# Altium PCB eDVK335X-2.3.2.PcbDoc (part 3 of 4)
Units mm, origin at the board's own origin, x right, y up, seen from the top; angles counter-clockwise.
Board outline 100.04 x 80.07 mm, 4 copper layers (Top Layer, Layer 1, Layer 2, Bottom Layer), stack 0.569 mm thick; 245 components, 272 nets, 1313 pads, 662 vias.
Unrouted connection lines stored in the file: 1.
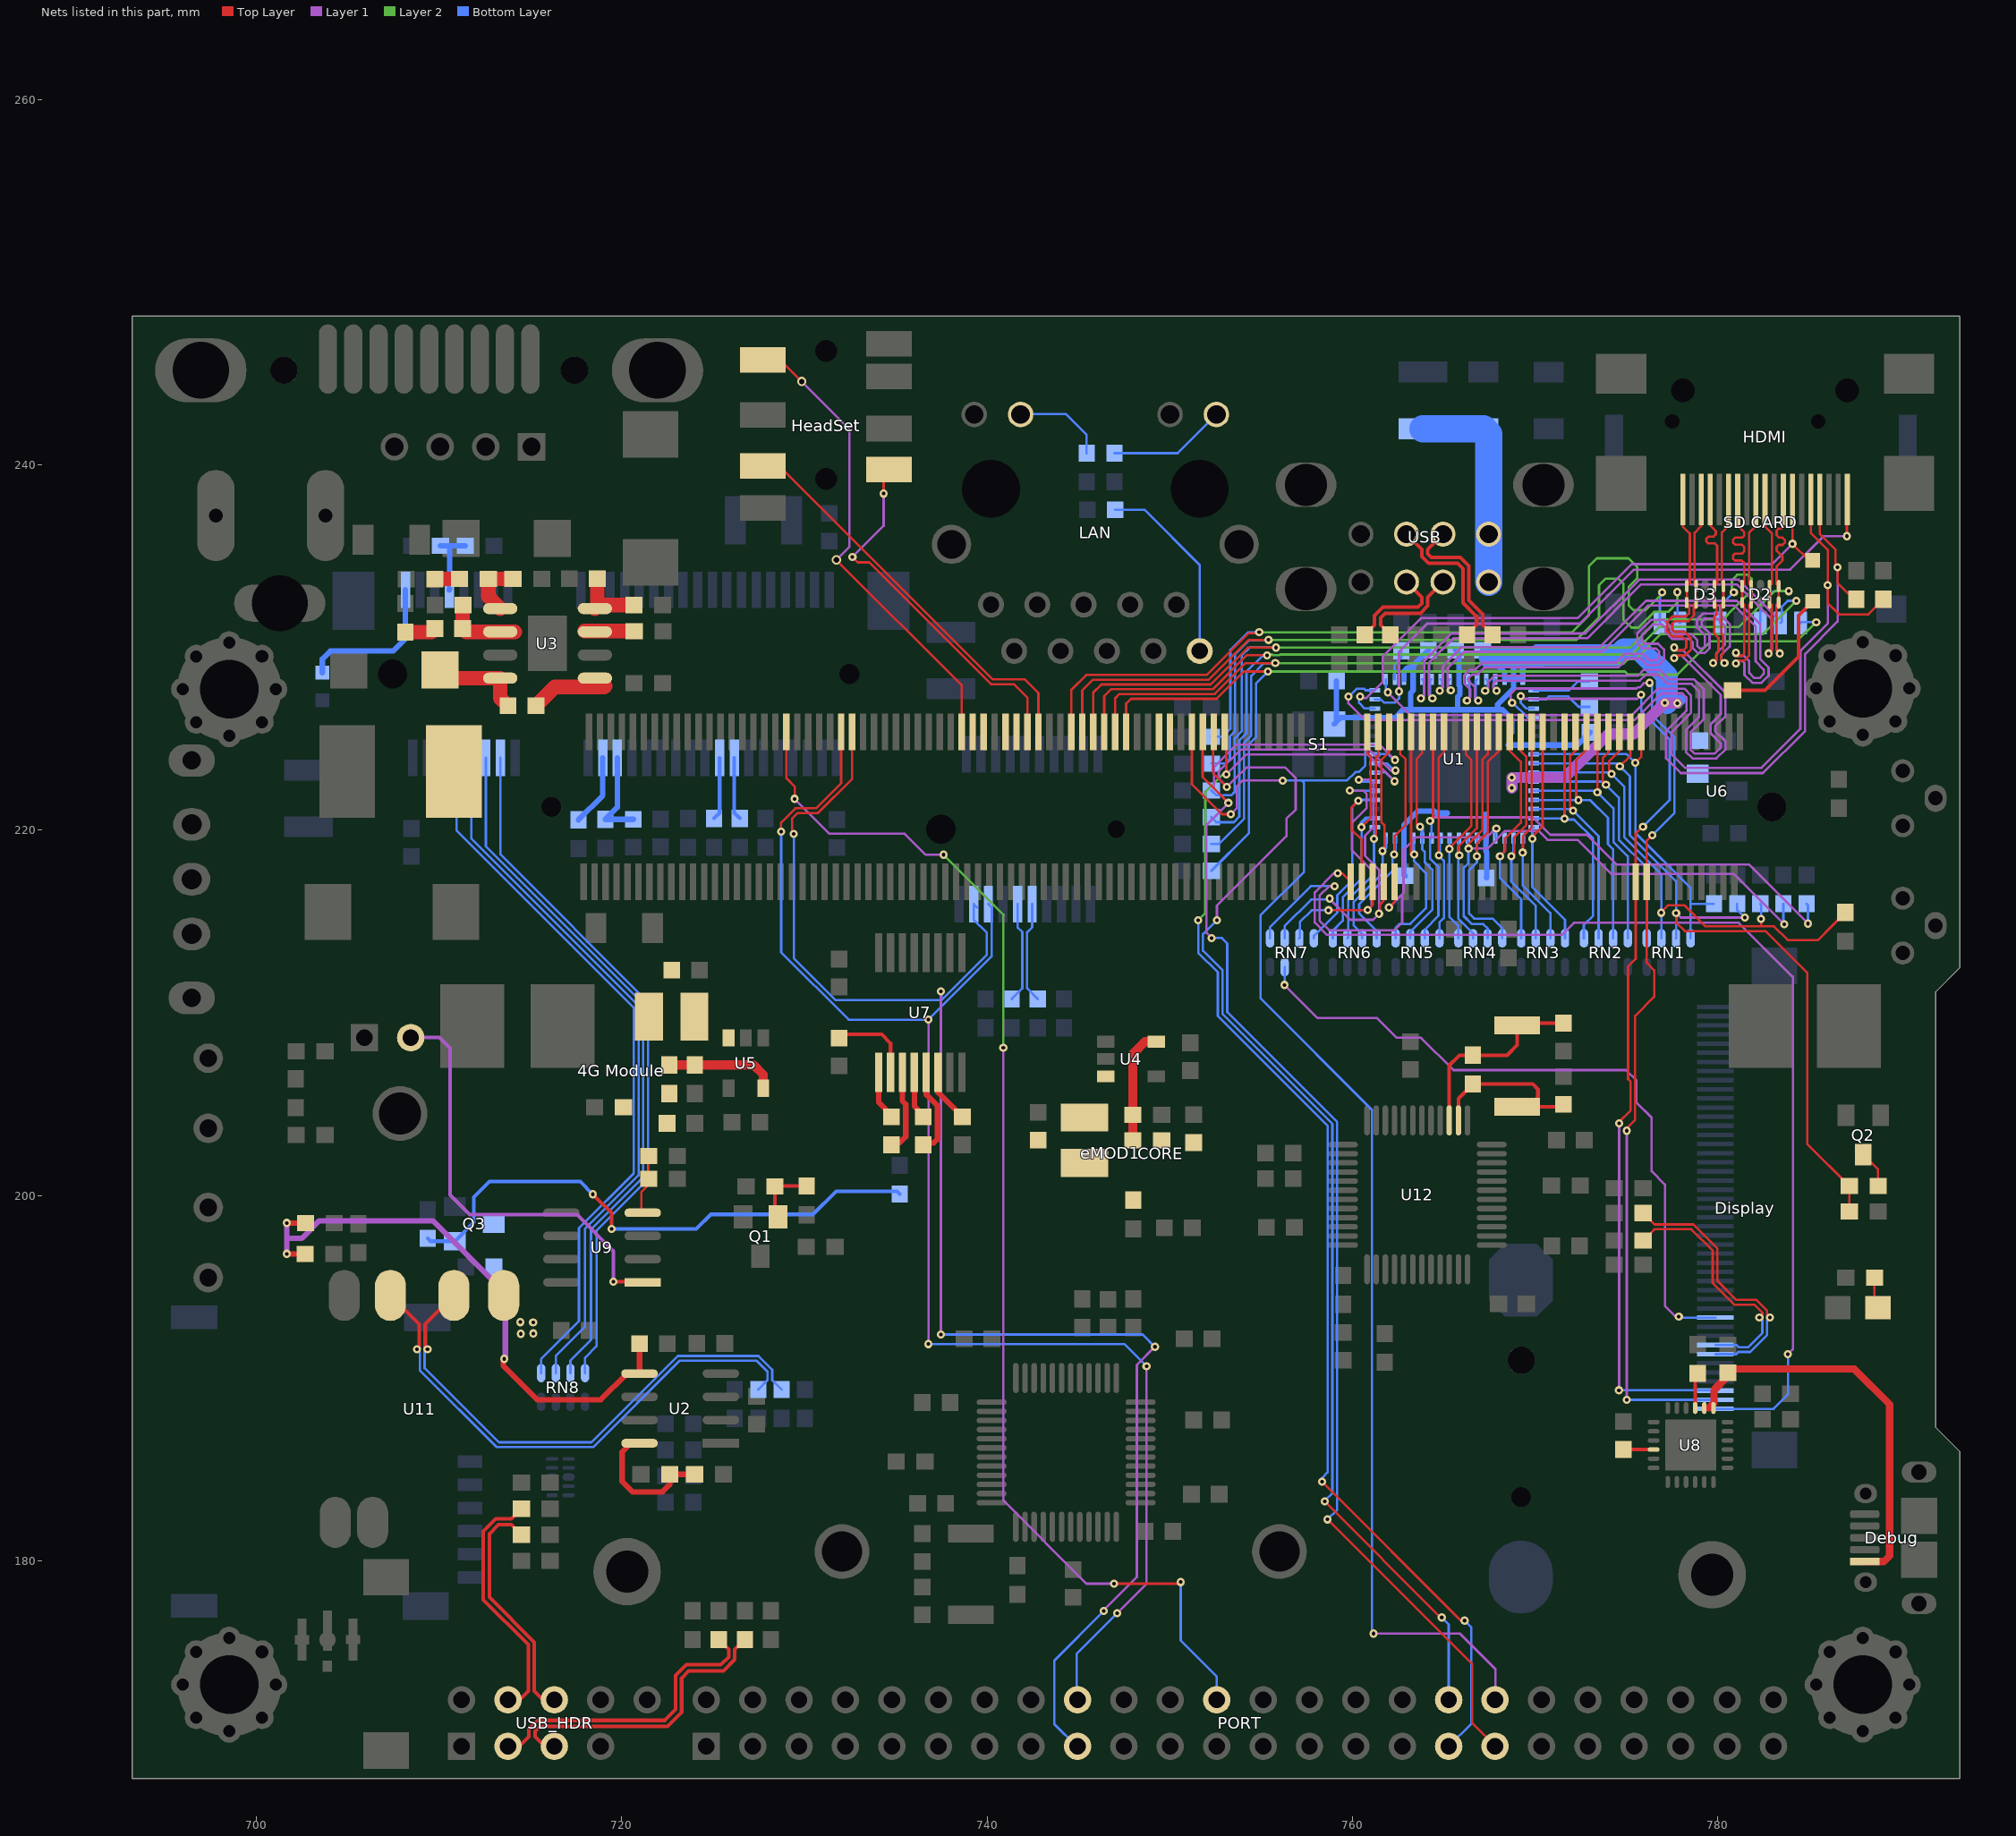
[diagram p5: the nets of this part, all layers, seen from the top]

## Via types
v1: diameter 0.45, hole 0.2, Top Layer to Bottom Layer, tented both sides, 424 vias
v2: diameter 0.7, hole 0.5, Top Layer to Bottom Layer, tented both sides, 146 vias
v3: diameter 0.45, hole 0.25, Top Layer to Bottom Layer, tented both sides, 55 vias
v4: diameter 0.5, hole 0.3, Top Layer to Bottom Layer, tented both sides, 17 vias
v5: diameter 0.7, hole 0.4, Top Layer to Bottom Layer, tented both sides, 13 vias
v6: diameter 0.66, hole 0.33, Top Layer to Bottom Layer, tented both sides, 4 vias
v7: diameter 0.75, hole 0.5, Top Layer to Bottom Layer, tented both sides, 1 vias
v8: diameter 0.5, hole 0.2, Top Layer to Bottom Layer, tented both sides, 1 vias
v9: diameter 0.45, hole 0.3, Top Layer to Bottom Layer, tented both sides, 1 vias

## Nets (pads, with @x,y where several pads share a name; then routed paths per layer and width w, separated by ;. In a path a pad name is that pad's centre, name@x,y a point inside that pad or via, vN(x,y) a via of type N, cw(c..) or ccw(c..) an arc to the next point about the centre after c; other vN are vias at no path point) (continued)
GPIO3_21: CORE.167 PORT.24 | length 68.9
  Top Layer w0.13: CORE.167@729.011,225.38 729.011,222.849 729.48,222.38 729.48,221.73 v1(729.47,221.72) ; v1(746.95,178.75) 750.51,178.75 v1(750.6,178.84)
  Layer 1 w0.13: v1(729.47,221.72) 731.38,219.81 735.49,219.81 736.64,218.66 v1(737.62,218.66) ; v1(740.89,208.09) 740.89,183.3 745.44,178.75 v1(746.95,178.75)
  Layer 2 w0.13: v1(737.62,218.66) 740.91,215.37 740.89,215.35 v1(740.89,208.09)
  Bottom Layer w0.13: v1(750.6,178.84) 750.6,175.64 752.57,173.67 PORT.24@752.57,172.39
HDMI_1V8: C1.1 C2.1 C3.1 C4.1 C5.1 C6.1 C7.1 C8.1 C25.1 S1.4 U1.5 U1.14 U1.29 U1.35 U1.36 U1.41 U1.46 U1.47 U1.48 U1.55 U6.2 | length 70.2
  Layer 1 w0.6: v1(768.72,222.315) 768.73,222.325 v1(768.73,222.88) 771.62,222.88 774.01,225.27 775.4,225.27 v1(777.1,226.97) 777.76,226.97 v1(777.78,226.95)
  Bottom Layer w0.3: S1.4@759.001,225.822 S1.4@759.13,225.95 ; C2.1@759.13,228.168 S1.4@759.13,225.95 ; U1.35@762.825,228.264 762.825,228.705 763.01,228.89 763.194,228.89 763.325,229.021 ; C1.1@762.88,217.502 762.825,217.557 U1.14@762.825,219.564 762.825,220.295 763.581,221.051 764.476,221.051 764.587,220.94 765.2,220.94 ; 763.19,226.6 763.19,227.52 763.325,227.655 U1.36@763.325,228.264 763.325,229.021 ; C6.1@764.162,229.858 763.325,229.021 ; C5.1@765.646,229.858 765.825,229.679 U1.41@765.825,228.264 765.825,227.935 765.89,227.87 765.89,227.439 765.76,227.309 765.76,226.664 765.82,226.604 765.82,226.594 ; 767.27,220.87 767.298,220.842 767.298,218.858 767.356,218.801 767.356,217.428 C3.1@767.325,217.397 ; C3.1@767.32,217.392 C3.1@767.325,217.397 ; C3.1@767.356,217.397 C3.1@767.325,217.397 ; 767.95,226.6 767.95,226.89 768.235,227.175 768.235,227.179 768.531,227.475 768.535,227.475 768.825,227.765 U1.47@768.825,228.264 ; 768.54,224.665 U1.55@769.925,224.665 772.304,224.665 C4.1@772.998,225.358 ; 768.71,225.35 768.71,226.1 768.216,226.594 765.82,226.594 ; 770.748,230.03 770.04,230.03 769.48,229.47 769.325,229.315 U1.48@769.325,228.264 U1.47@768.825,228.264 ; S1.4@759.13,225.95 759.344,226.164 U1.29@761.225,226.164 762.334,226.164 762.764,226.594 765.82,226.594 ; U1.47@768.825,228.264 768.825,229.195 768.55,229.47 768.162,229.858 C7.1@767.13,229.858 767.518,229.47 768.325,228.663 U1.46@768.325,228.264 U1.47@768.825,228.264
  Bottom Layer w0.6: v1(777.1,226.97) 777.205,226.97 777.79,226.97 777.94,227.12
  Bottom Layer w1.2: C7.1@767.518,229.47 768.55,229.47 769.48,229.47 770.12,229.47 770.23,229.58 774.549,229.58 774.864,229.895 775.656,229.895 775.668,229.882 775.704,229.882 776.561,229.025 776.656,229.025 777.215,228.466 777.215,226.98 v1@777.205,226.97
HDMI_CEC: D1.1 HDMI.13 U1.30 | length 33.2
  Top Layer w0.13: HDMI.13@784.09,238.099 v1(784.09,235.68) 784.985,234.785 D1.1@785.2,234.785
  Layer 1 w0.13: v1@760.36,227.23 760.37,227.24 760.77,227.24 761.66,228.13 761.66,229.52 763.75,231.61 772.326,231.61 775.286,234.57 782.98,234.57 v1(784.09,235.68)
  Bottom Layer w0.13: v1@760.36,227.23 760.36,226.98 760.675,226.665 U1.30@761.225,226.665
  other v1: 760.418,227.32
HDMI_CEC_D: D1.2 R36.1 | length 7.7
  Top Layer w0.2: R36.1@780.807,227.66 782.59,227.66 784.42,229.49 784.42,231.755 D1.2@785.2,232.535
HDMI_DSCL: HDMI.15 R34.2 U1.33 | length 48.7
  Top Layer w0.13: HDMI.15@785.09,238.099 785.09,236.28 786.02,235.35 v1(786.02,233.42) 786.02,232.44 786.64,231.82 788.241,231.82 R34.2@789.064,232.643
  Layer 1 w0.13: v1(761.94,227.55) 763.19,226.3 775.29,226.3 776.74,227.75 778.168,227.75 778.54,227.378 778.54,226.432 777.47,225.362 777.47,224.16 778.21,223.42 782.392,223.42 784.52,225.548 784.52,229.82 786.02,231.32 v1(786.02,233.42)
  Bottom Layer w0.13: U1.33@761.825,228.264 761.825,227.765 761.94,227.65 v1(761.94,227.55)
HDMI_DSDA: HDMI.16 R35.2 U1.32 | length 50.4
  Top Layer w0.13: HDMI.16@785.59,238.099 785.59,236.22 786.45,235.36 786.45,234.5 v1(786.56,234.39) 786.56,233.55 787.467,232.643 R35.2@787.58,232.643
  Layer 1 w0.13: v1@759.778,227.3 759.778,226.942 760.68,226.04 775.454,226.04 776.904,227.49 778.06,227.49 778.28,227.27 778.28,226.54 777.17,225.43 777.17,223.93 777.97,223.13 782.47,223.13 784.78,225.44 784.78,229.656 786.56,231.436 v1(786.56,234.39)
  Bottom Layer w0.13: v1@759.778,227.3 759.91,227.3 759.91,227.38 759.9,227.39 759.94,227.43 759.94,227.444 760.226,227.73 ; 760.226,227.74 760.645,227.74 760.72,227.665 U1.32@761.225,227.665
  other v1: 759.778,227.32
HDMI_HPD: HDMI.19 U1.31 | length 33.2
  Top Layer w0.13: v1(787.07,236.1) 787.07,238.04 787.11,238.08 HDMI.19@787.09,238.099
  Layer 1 w0.13: v1@762.55,227.6 762.55,229.76 764.1,231.31 772.45,231.31 775.41,234.27 783.96,234.27 785.79,236.1 v1(787.07,236.1)
  Bottom Layer w0.13: U1.31@761.225,227.164 761.556,227.164 761.73,226.99 762.331,226.99 762.558,227.218 v1(762.558,227.6)
HDMI_INT: R38.2 U1.50 | length 3.4
  Bottom Layer w0.13: U1.50@769.925,227.164 770.594,227.164 770.76,227.33 771.81,227.33 772.385,226.755 R38.2@772.973,226.755
HDMI_SWING: R37.1 U1.34 | length 1.7
  Bottom Layer w0.13: U1.34@762.325,228.264 762.31,228.279 762.31,229.08 762.678,229.448 R37.1@762.678,229.833
HDMI_TX0_N: D2.2 D2.9 HDMI.9 U1.39 | length 37.5
  Top Layer w0.13: v1(780.99,229.13) 780.99,229.27 781.01,229.29 781.45,229.29 781.715,229.555 781.715,232.348 D2.2@781.835,232.468 D2.9@781.835,233.368 781.715,233.488 781.715,236.285 782.09,236.66 HDMI.9@782.09,238.099
  Layer 1 w0.13: v1@764.765,227.66 v1@764.91,227.805 ; v1(764.775,227.64) 764.95,227.815 764.95,228.987 765.992,230.03 773.54,230.03 776.07,232.56 781.038,232.56 782.33,231.268 782.33,229.358 782.78,228.908 782.78,228.46 782.39,228.07 781.89,228.07 781.46,228.5 781.46,229.15 781.32,229.29 781.15,229.29 v1(780.99,229.13)
  Bottom Layer w0.13: v1@764.765,227.66 764.77,227.66 v1@764.91,227.8 ; U1.39@764.825,228.264 764.91,228.179 v1@764.91,227.8 ; v1@764.91,227.7 v1@764.91,227.8
HDMI_TX0_P: D2.1 D2.10 HDMI.7 U1.40 | length 37.6
  Top Layer w0.13: v1(780.99,229.71) 780.99,229.57 781.01,229.55 781.33,229.55 781.455,229.675 781.455,232.348 D2.1@781.335,232.468 D2.10@781.335,233.368 781.455,233.488 781.45,233.493 781.45,234.63 781.315,234.765 780.935,234.765 780.835,234.865 780.835,235.035 780.945,235.145 781.325,235.145 781.455,235.275 781.455,235.505 781.32,235.64 780.94,235.64 780.84,235.74 780.84,235.91 780.95,236.02 781.33,236.02 781.455,236.145 781.455,236.315 781.09,236.68 HDMI.7@781.09,238.099
  Layer 1 w0.13: v1@765.24,227.705 v1@765.24,227.805 ; v1(765.385,227.66) v1@765.24,227.805 ; v1(780.99,229.71) 781.15,229.55 781.428,229.55 781.72,229.258 781.72,228.608 781.998,228.33 782.282,228.33 782.52,228.568 782.52,228.8 782.07,229.25 782.07,231.16 780.93,232.3 776.178,232.3 773.648,229.77 766.1,229.77 765.21,228.88 765.21,227.835 v1@765.24,227.805
  Bottom Layer w0.13: v1@765.24,227.7 v1@765.24,227.8 ; U1.40@765.325,228.264 765.24,228.179 v1@765.24,227.8 ; v1(765.385,227.66) 765.38,227.66 v1@765.24,227.8
HDMI_TX1_N: D3.5 D3.6 HDMI.6 U1.42 | length 37.6
  Top Layer w0.13: v1(780.365,229.15) 780.17,229.345 780.17,229.542 780.3,229.672 780.3,230.64 780.19,230.75 780.19,232.348 D3.5@780.31,232.468 D3.6@780.31,233.368 780.225,233.453 780.225,236.315 780.59,236.68 HDMI.6@780.59,238.099
  Layer 1 w0.13: v1(766.265,227.1) v1@766.41,227.245 ; v1@766.41,227.075 v1@766.41,227.245 ; v1(780.365,229.15) 780.185,229.33 780.185,229.587 780.66,230.062 780.66,231.278 780.078,231.86 779.182,231.86 778.86,231.538 778.86,231.11 779.29,230.68 779.29,230.07 779.18,229.96 779.01,229.96 778.88,230.09 778.88,230.405 778.545,230.74 777.608,230.74 777.4,230.948 777.4,231.178 777.324,231.254 777.134,231.444 777.058,231.52 776.332,231.52 ; v1@766.41,227.245 766.445,227.28 766.445,227.72 766.11,228.055 766.11,228.458 766.432,228.78 766.72,228.78 767.12,229.18 774.44,229.18 774.92,229.66 775.898,229.66 776.258,229.3 776.66,229.3 776.8,229.44 776.8,229.78 776.63,229.95 775.882,229.95 775.666,230.166 775.59,230.242 775.59,230.778 775.666,230.854 776.256,231.444 ; 776.256,231.444 776.332,231.52 ; 776.256,231.444 776.332,231.52
  Bottom Layer w0.13: v1(766.265,227.1) v1@766.41,227.245 ; U1.42@766.325,228.264 766.41,228.18 v1@766.41,227.245 ; v1@766.41,227.075 v1@766.41,227.245
HDMI_TX1_P: D3.4 D3.7 HDMI.4 U1.43 | length 37.5
  Top Layer w0.13: HDMI.4@779.59,238.099 779.59,236.68 779.895,236.375 779.895,236.205 779.77,236.08 779.49,236.08 779.38,235.97 779.38,235.8 779.48,235.7 779.833,235.7 ; v1(779.745,229.15) 779.91,229.315 779.91,229.65 780.04,229.78 780.04,230.532 779.8,230.772 779.8,231.67 779.93,231.8 779.93,232.348 D3.4@779.81,232.468 D3.7@779.81,233.368 779.965,233.523 779.965,235.58 779.845,235.7
  Layer 1 w0.13: v1@766.74,227.075 v1@766.74,227.245 ; v1(766.885,227.1) v1@766.74,227.245 ; v1(779.745,229.15) 779.925,229.33 779.925,229.695 780.4,230.17 780.4,231.17 779.97,231.6 779.29,231.6 779.12,231.43 779.12,231.218 779.55,230.788 779.55,229.962 779.288,229.7 778.902,229.7 778.62,229.982 778.62,230.298 778.438,230.48 777.5,230.48 777.14,230.84 777.14,231.07 776.95,231.26 776.44,231.26 775.85,230.67 775.85,230.35 775.99,230.21 776.738,230.21 777.06,229.888 777.06,229.332 776.768,229.04 776.15,229.04 775.79,229.4 775.028,229.4 774.548,228.92 767.228,228.92 766.828,228.52 766.54,228.52 766.37,228.35 766.37,228.162 766.705,227.828 766.705,227.28 v1@766.74,227.245
  Bottom Layer w0.13: v1@766.74,227.075 v1@766.74,227.245 ; U1.43@766.825,228.264 766.74,228.18 v1@766.74,227.245 ; v1(766.885,227.1) v1@766.74,227.245
HDMI_TX2_N: D3.2 D3.9 HDMI.3 U1.44 | length 37.5
  Top Layer w0.13: v1(777.62,229.42) 777.62,229.57 778.208,229.57 778.459,229.821 778.535,229.897 778.535,230.503 778.459,230.579 778.168,230.87 777.63,230.87 777.5,231 777.5,231.31 777.63,231.44 778.368,231.44 778.69,231.762 778.69,232.348 D3.2@778.81,232.468 D3.9@778.81,233.368 778.73,233.448 778.73,236.29 779.09,236.65 HDMI.3@779.09,238.099
  Layer 1 w0.13: v1(767.265,227.64) 767.445,227.82 767.445,228.118 767.777,228.45 775.63,228.45 775.96,228.78 776.838,228.78 777.348,228.27 778.688,228.27 779.154,227.804 779.23,227.728 779.23,226.082 779.154,226.006 778.52,225.372 778.52,224.4 778.73,224.19 779.812,224.19 780.16,224.538 780.16,224.75 779.61,225.3 779.61,225.81 780.16,226.36 780.16,227.42 778,229.58 777.78,229.58 v1(777.62,229.42)
  Bottom Layer w0.13: v1(767.265,227.64) 767.27,227.64 v1@767.41,227.78 ; U1.44@767.325,228.264 767.41,228.18 v1@767.41,227.78 ; v1@767.41,227.68 v1@767.41,227.78
HDMI_TX2_P: D3.1 D3.10 HDMI.1 U1.45 | length 37.5
  Top Layer w0.13: v1(777.62,230) 777.62,229.85 778.12,229.85 778.275,230.005 778.275,230.395 778.06,230.61 777.522,230.61 777.24,230.892 777.24,231.418 777.522,231.7 778.26,231.7 778.43,231.87 778.43,232.348 D3.1@778.31,232.468 D3.10@778.31,233.368 778.47,233.528 778.47,236.24 778.09,236.62 HDMI.1@778.09,238.099
  Layer 1 w0.13: v1(767.885,227.64) 767.705,227.82 767.705,228.01 767.885,228.19 775.738,228.19 776.068,228.52 776.73,228.52 777.24,228.01 778.58,228.01 778.97,227.62 778.97,226.19 778.67,225.89 778.26,225.48 778.26,224.292 778.622,223.93 779.92,223.93 780.42,224.43 780.42,224.86 779.87,225.41 779.87,225.7 780.42,226.25 780.42,227.528 778.108,229.84 777.78,229.84 v1(777.62,230)
  Bottom Layer w0.13: v1@767.74,227.68 v1@767.74,227.78 ; U1.45@767.825,228.264 767.74,228.18 v1@767.74,227.78 ; v1(767.885,227.64) 767.88,227.64 v1@767.74,227.78
HDMI_TXC_N: D2.5 D2.6 HDMI.12 U1.37 | length 37.5
  Top Layer w0.13: v1(783.395,229.68) 783.215,229.86 ; HDMI.12@783.59,238.099 783.59,236.61 783.49,236.51 783.33,236.51 783.22,236.4 783.22,236.15 783.35,236.02 783.55,236.02 783.67,235.9 783.67,235.74 783.55,235.62 783.33,235.62 783.22,235.51 783.22,235.31 783.54,234.99 783.54,234.77 783.22,234.45 783.22,233.483 D2.6@783.335,233.368 D2.5@783.335,232.468 783.215,232.348 783.215,230.032 ; 783.215,229.86 783.215,230.032 ; 783.215,229.86 783.215,230.032
  Layer 1 w0.13: v1(763.755,227.22) 763.935,227.4 763.935,229.285 765.42,230.77 772.75,230.77 775.7,233.72 781.15,233.72 783.215,231.655 783.215,229.86 v1(783.395,229.68) ; v1@783.27,229.68 783.27,229.64 v1@783.395,229.64
  Bottom Layer w0.13: v1@763.765,227.1 763.78,227.1 763.78,227.22 763.91,227.35 763.91,228.179 U1.37@763.825,228.264
HDMI_TXC_P: D2.4 D2.7 HDMI.10 U1.38 | length 37.5
  Top Layer w0.13: HDMI.10@782.59,238.099 782.59,236.63 782.96,236.26 782.96,233.493 D2.7@782.835,233.368 D2.4@782.835,232.468 782.955,232.348 782.955,232.295 ; v1(782.775,229.68) 782.955,229.86 782.955,232.295 ; 782.955,230.14 782.955,232.295
  Layer 1 w0.13: v1(764.375,227.22) 764.195,227.4 764.195,229.177 765.528,230.51 772.858,230.51 775.808,233.46 781.042,233.46 782.955,231.547 782.955,229.86 v1(782.775,229.68) ; v1@782.775,229.64 782.9,229.64 v1@782.9,229.68
  Bottom Layer w0.13: U1.38@764.325,228.264 764.24,228.179 764.24,227.35 v1@764.37,227.22
HP-L: CORE.123 HeadSet.8 | length 20.3
  Top Layer w0.13: v1(732.63,234.96) 732.924,234.666 733.546,234.666 740.212,228 741.46,228 742.211,227.249 CORE.123@742.211,225.38 ; v1(734.34,238.43) 734.34,239.45 HeadSet.8@734.63,239.74
  Layer 1 w0.13: v1(732.63,234.96) 734.34,236.67 v1(734.34,238.43)
HP-R: CORE.121 HeadSet.3 | length 22.4
  Top Layer w0.13: HeadSet.3@727.73,239.94 728.64,239.94 740.32,228.26 742.07,228.26 742.811,227.519 CORE.121@742.811,225.38
HS: Display.11 RN7.3 | length 38.4
  Layer 1 w0.13: v1(756.287,211.53) 758.097,209.72 761.345,209.72 762.425,208.64 763.76,208.64 765.53,206.87 774.98,206.87 775.53,206.32 775.53,205.11 776.38,204.26 776.38,201.33 777.11,200.6 777.11,193.96 777.65,193.42 777.85,193.42 777.87,193.4 777.87,193.371 v1(777.868,193.37)
  Bottom Layer w0.13: v1@756.29,211.533 RN7.3@756.29,212.509 ; v1(777.868,193.37) 777.919,193.319 Display.11@779.871,193.319
HUSB0_N: eMOD1.11 R60.1 | length 5.6
  Bottom Layer w0.13: R60.1@741.347,210.757 741.93,211.341 741.93,214.43 741.67,214.69 eMOD1.11@741.67,215.96
HUSB0_P: eMOD1.9 R61.1 | length 5.6
  Bottom Layer w0.13: eMOD1.9@742.47,215.96 742.47,214.69 742.19,214.41 742.19,211.341 R61.1@742.773,210.757
HUSB1_N: "4G Module.36" R53.1 | length 3.4
  Bottom Layer w0.2: R53.1@725.046,220.647 725.36,220.961 725.36,223.96
HUSB1_P: "4G Module.38" R54.1 | length 3.4
  Bottom Layer w0.2: 726.16,223.96 726.16,220.949 R54.1@726.462,220.647
HUSB2_N: R51.1 USB.U2 | length 5.7
  Top Layer w0.2: R51.1@762.075,230.702 761.542,231.236 761.542,231.622 761.8,231.88 763.722,231.88 764.125,232.283 764.125,232.755 USB.U2@764.96,233.59
HUSB2_P: R52.1 USB.U3 | length 5.7
  Top Layer w0.2: R52.1@760.678,230.702 761.212,231.236 761.212,231.758 761.663,232.21 763.585,232.21 763.795,232.42 763.795,232.755 USB.U3@762.96,233.59
HUSB3_N: R42.1 USB_HDR.3 | length 16.6
  Top Layer w0.2: USB_HDR.3@713.77,169.85 714.39,169.85 714.92,170.38 714.92,170.797 715.393,171.27 722.36,171.27 722.95,171.86 722.95,173.73 723.53,174.31 725.43,174.31 725.857,174.737 725.857,175.148 R42.1@725.309,175.697
HUSB3_P: R43.1 USB_HDR.5 | length 16.5
  Top Layer w0.2: USB_HDR.5@716.31,169.85 715.78,169.85 715.25,170.38 715.25,170.66 715.53,170.94 722.497,170.94 723.28,171.723 723.28,173.593 723.667,173.98 725.567,173.98 726.187,174.6 726.187,175.148 R43.1@726.735,175.697
HUSB4_N: Display.8 R110.1 | length 14
  Top Layer w0.13: R110.1@775.909,197.532 776.533,198.157 778.553,198.157 779.72,196.99 779.72,195.212 780.17,194.762 780.826,194.106 780.902,194.03 782.002,194.03 782.44,193.592 v1@782.44,193.46 ; v1(782.28,193.33) 782.31,193.33 v1@782.44,193.46 ; v1@782.44,193.395 v1@782.44,193.46
  Bottom Layer w0.13: Display.8@779.871,191.819 781.011,191.819 781.131,191.699 781.669,191.699 782.44,192.47 782.44,193.17 v1(782.28,193.33)
HUSB4_P: Display.7 R111.1 | length 14.8
  Top Layer w0.13: R111.1@775.909,199.041 776.533,198.417 778.661,198.417 779.98,197.098 779.98,195.32 781.01,194.29 782.11,194.29 782.7,193.7 782.7,193.46 782.83,193.33 v1(782.86,193.33)
  Bottom Layer w0.13: Display.7@779.871,191.319 781.009,191.319 781.129,191.439 781.776,191.439 782.7,192.362 782.7,193.17 v1(782.86,193.33)
HUSB5_N: R96.1 U11.2 | length 29
  Top Layer w0.2: v1(709.367,191.59) 709.242,191.715 709.242,192.963 U11.2@710.815,194.535
  Bottom Layer w0.13: v1(709.367,191.59) 709.207,191.43 709.207,190.553 713.27,186.49 718.34,186.49 723.07,191.22 727.488,191.22 728.24,190.468 728.24,189.887 R96.1@728.75,189.377
HUSB5_P: R97.1 U11.3 | length 29
  Top Layer w0.2: U11.3@707.34,194.535 708.912,192.963 708.912,191.715 v1(708.787,191.59)
  Bottom Layer w0.13: v1(708.787,191.59) 708.947,191.43 708.947,190.445 713.162,186.23 718.448,186.23 723.178,190.96 727.38,190.96 727.98,190.36 727.98,189.887 R97.1@727.47,189.377
HUSB6_N: R94.1 USB.D2 | length 8.3
  Top Layer w0.2: USB.D2@764.96,236.21 764.125,235.375 764.125,235.13 764.315,234.94 765.907,234.94 766.38,234.467 766.38,232.587 767.13,231.837 767.13,231.236 R94.1@767.663,230.702
HUSB6_P: R95.1 USB.D3 | length 8.3
  Top Layer w0.2: USB.D3@762.96,236.21 763.795,235.375 763.795,234.993 764.178,234.61 765.77,234.61 766.05,234.33 766.05,232.45 766.8,231.7 766.8,231.236 R95.1@766.266,230.702
HUSB7_N: R62.1 USB_HDR.4 | length 13.7
  Top Layer w0.2: USB_HDR.4@713.77,172.39 714.39,172.39 714.88,172.88 714.88,175.41 712.42,177.87 712.42,181.617 713.111,182.308 713.958,182.308 R62.1@714.506,182.856
HUSB7_P: R63.1 USB_HDR.6 | length 13.1
  Top Layer w0.2: R63.1@714.506,181.43 713.958,181.978 713.248,181.978 712.75,181.48 712.75,178.007 715.21,175.547 715.21,172.88 715.7,172.39 USB_HDR.6@716.31,172.39
I2C0_SCL: CORE.18 Display.2 U1.52 | length 56.1
  Top Layer w0.13: v1(775.018,203.55) 775.01,203.55 774.96,203.6 774.96,203.63 775.478,204.148 775.478,209.838 776.52,210.88 776.52,212.33 776.111,212.739 CORE.18@776.111,217.18 776.111,219.431 v1(776.41,219.73)
  Layer 1 w0.13: v1(768.74,226.97) 768.67,227.04 768.67,227.47 768.96,227.76 775.555,227.76 775.624,227.83 775.745,227.83 775.985,228.07 v1(776.26,228.07) ; v1(775.018,203.55) 775.018,188.822 v1(775.02,188.82)
  Bottom Layer w0.13: v1@768.73,227.03 769.596,226.164 U1.52@769.925,226.164 ; v1(775.02,188.82) 779.87,188.82 Display.2@779.871,188.819 ; v1(776.26,228.07) 776.41,227.92 776.41,226.3 777.63,225.08 777.63,220.95 v1(776.41,219.73)
I2C0_SDA: CORE.20 Display.3 U1.51 | length 53.4
  Top Layer w0.13: v1(774.598,203.96) 774.56,203.96 774.56,203.99 775.218,204.648 775.218,206.249 775.093,206.374 775.093,212.543 775.511,212.961 CORE.20@775.511,217.18 775.511,219.821 775.88,220.19 v1(775.908,220.19)
  Layer 1 w0.13: v1(769.208,227.34) 769.348,227.2 775.588,227.2 v1(775.798,227.41) ; v1(774.59,189.34) 774.598,189.348 v1(774.598,203.96)
  Bottom Layer w0.13: v1@769.208,227.46 v1(769.208,227.34) 769.208,227.032 769.21,227.03 769.21,226.974 769.52,226.665 U1.51@769.925,226.665 ; v1(774.59,189.34) 779.85,189.34 Display.3@779.871,189.319 ; v1(775.798,227.41) 775.8,227.41 775.81,227.4 775.81,226.7 775.81,226.532 777.37,224.972 777.37,221.651 v1(775.908,220.19)
I2C1_SCL: CORE.157 eMOD1.15 PORT.18 | length 81.8
  Top Layer w0.13: v1(728.73,219.92) 728.72,219.92 728.72,220.41 729.51,221.2 730.64,221.2 732.011,222.571 CORE.157@732.011,225.38
  Layer 1 w0.13: v1(736.79,191.87) v1(736.79,209.63) ; v1(747.12,177.13) 748.73,178.74 v1(748.73,190.65)
  Bottom Layer w0.13: v1(728.73,219.92) 728.73,213.32 732.42,209.63 v1(736.79,209.63) 740.25,213.09 740.25,215.78 eMOD1.15@740.07,215.96 ; v1(736.79,191.87) 747.51,191.87 v1(748.73,190.65) ; PORT.18@745.55,172.39 744.91,173.03 744.91,174.92 v1(747.12,177.13)
I2C1_SDA: CORE.155 eMOD1.17 PORT.17 | length 86.9
  Top Layer w0.13: v1(729.42,219.8) 729.42,219.85 729.32,219.95 729.32,220.63 729.63,220.94 730.748,220.94 732.611,222.804 CORE.155@732.611,225.38
  Layer 1 w0.13: v1(737.47,192.39) v1(737.47,211.18) ; v1(746.39,177.25) 746.39,177.3 748.2,179.11 748.2,190.73 v1(749.19,191.72)
  Bottom Layer w0.13: v1(729.42,219.8) 729.42,212.998 731.718,210.7 737.492,210.7 ; v1(737.47,192.39) 748.52,192.39 v1(749.19,191.72) ; v1(737.47,211.18) 737.492,211.158 737.492,210.7 ; eMOD1.17@739.46,215.77 eMOD1.17@739.27,215.96 739.27,215.1 739.99,214.38 739.99,213.198 737.492,210.7 ; PORT.17@745.55,169.85 PORT.17@744.95,169.85 744.89,169.85 743.68,171.06 743.68,174.54 v1(746.39,177.25)
LCD_DATA0: CORE.27 RN2.4 U1.60 | length 15.5
  Top Layer w0.13: v1(773.41,222.08) 773.411,222.081 CORE.27@773.411,225.38
  Bottom Layer w0.13: U1.60@769.925,222.164 773.326,222.164 v1(773.41,222.08) 774.288,221.202 774.288,219.365 775.076,218.577 RN2.4@775.076,214.083
LCD_DATA1: CORE.25 RN1.1 U1.59 | length 16.6
  Top Layer w0.13: v1(773.878,222.5) 773.808,222.429 773.711,222.526 773.711,223.96 774.011,224.26 CORE.25@774.011,225.38
  Bottom Layer w0.13: U1.59@769.925,222.665 773.713,222.665 v1(773.878,222.5) 774.588,221.79 774.588,219.489 776.113,217.964 RN1.1@776.113,214.083
LCD_DATA2: CORE.23 R1.2 R10.2 RN1.2 U1.58 | length 30
  Top Layer w0.13: v1(774.178,223.08) 774.058,223.2 774.058,223.787 774.611,224.34 CORE.23@774.611,225.38 ; v1(776.908,215.48) v1@776.91,215.478 ; v1@776.91,215.44 v1@776.91,215.478 ; v1(782.37,215.15) 782.37,214.74 ; R1.2@786.98,215.497 786.223,214.74 786.223,214.723 785.49,213.99 783.83,213.99 783.08,214.74 782.37,214.74 ; v1@776.91,215.478 776.91,215.53 777.27,215.89 778.19,215.89 779.34,214.74 782.37,214.74
  Bottom Layer w0.13: U1.58@769.925,223.164 774.094,223.164 v1(774.178,223.08) 774.888,222.37 774.888,219.613 776.913,217.588 RN1.2@776.913,214.083 ; R10.2@782.33,215.973 782.37,215.933 v1(782.37,215.15)
LCD_DATA3: CORE.21 R2.2 R3.2 R9.2 RN1.3 U1.57 | length 45.4
  Top Layer w0.13: v1(774.638,223.5) 774.61,223.471 775.211,224.071 CORE.21@775.211,225.38 ; v1@777.72,215.52 v1(777.72,215.47) 777.72,214.96 778.2,214.48 782.62,214.48 784.9,212.2 784.9,202.833 R2.2@787.203,200.53 R3.2@787.203,199.12
  Layer 1 w0.13: v1(777.72,215.47) 777.97,215.22 v1(781.48,215.22)
  Bottom Layer w0.13: U1.57@769.925,223.665 774.473,223.665 v1(774.638,223.5) 775.188,222.95 775.188,219.737 777.72,217.206 v1(777.72,215.47) ; RN1.3@777.713,214.083 777.72,214.09 v1(777.72,215.47) ; v1@777.777,215.47 v1(777.72,215.47) ; R9.2@781.06,215.973 781.06,215.64 v1(781.48,215.22)
LCD_DATA4: CORE.19 R7.2 RN1.4 U1.56 | length 19.7
  Top Layer w0.13: v1(775.488,223.69) 775.48,223.69 775.811,224.021 CORE.19@775.811,225.38
  Bottom Layer w0.13: U1.56@769.925,224.164 775.014,224.164 v1(775.488,223.69) 775.488,219.862 778.513,216.837 778.513,215.98 ; RN1.4@778.513,214.083 778.513,215.98 ; R7.2@779.79,215.973 778.521,215.973 778.513,215.98
LCD_DATA5: CORE.47 R11.2 RN4.3 U1.7 | length 34.5
  Top Layer w0.13: v1(766.358,219) 766.289,218.93 766.24,218.93 766.334,219.024 766.334,219.21 767.111,219.987 767.111,223.86 767.411,224.16 CORE.47@767.411,225.38
  Layer 1 w0.13: v1(766.358,219) 767.4,219 768.36,219.96 770.19,219.96 770.68,219.47 772.32,219.47 774.19,217.6 780.89,217.6 v1(783.64,214.85)
  Bottom Layer w0.13: U1.7@766.325,219.564 766.325,219.033 v1(766.358,219) 766.351,218.992 766.351,218.195 766.09,217.934 766.09,215.306 766.536,214.86 767.165,214.86 767.402,214.623 RN4.3@767.402,214.083 ; R11.2@783.59,215.973 783.59,214.9 v1(783.64,214.85)
LCD_DATA6: CORE.45 RN4.4 U1.6 | length 14.4
  Top Layer w0.13: v1(766.811,218.575) 766.725,218.66 766.818,218.753 766.818,219.27 767.411,219.863 767.411,223.736 768.011,224.336 CORE.45@768.011,225.38
  Bottom Layer w0.13: U1.6@766.825,219.564 766.811,219.55 766.818,219.55 766.818,218.583 v1(766.811,218.575) 766.811,218.231 766.39,217.81 766.39,215.43 766.66,215.16 767.67,215.16 768.202,214.628 RN4.4@768.202,214.083
LCD_DATA7: CORE.43 RN3.1 U1.3 | length 13.7
  Top Layer w0.13: v1(768.078,218.58) 768.199,218.58 768.199,218.731 768.36,218.892 768.36,219.549 769.22,220.409 769.22,223.741 768.611,224.35 CORE.43@768.611,225.38
  Bottom Layer w0.13: U1.3@768.325,219.564 768.325,218.856 768.078,218.61 v1(768.078,218.58) 768.078,217.382 769.239,216.221 RN3.1@769.239,214.083
LCD_DATA8: CORE.41 RN3.2 U1.2 | length 13.6
  Top Layer w0.13: v1(768.698,218.58) 768.73,218.548 768.73,218.47 768.86,218.6 768.86,219.624 769.511,220.275 769.511,224.04 769.211,224.34 CORE.41@769.211,225.38
  Bottom Layer w0.13: U1.2@768.825,219.564 768.825,218.706 v1(768.698,218.58) 768.698,217.186 770.039,215.845 RN3.2@770.039,214.083
LCD_DATA9: CORE.39 RN3.3 U1.1 | length 12.9
  Top Layer w0.13: v1(769.32,218.78) 769.32,218.85 769.34,218.87 769.34,219.68 769.811,220.151 CORE.39@769.811,225.38
  Bottom Layer w0.13: U1.1@769.325,219.564 769.325,218.785 v1(769.32,218.78) 769.32,216.989 770.839,215.47 RN3.3@770.839,214.083
LCD_DATA10: CORE.37 RN3.4 U1.64 | length 13
  Top Layer w0.13: v1(769.848,219.53) 769.83,219.53 769.78,219.58 770.411,220.211 CORE.37@770.411,225.38
  Bottom Layer w0.13: U1.64@769.925,220.164 769.848,220.088 v1(769.848,219.53) 769.848,216.884 771.639,215.094 RN3.4@771.639,214.083
LCD_DATA11: CORE.63 RN6.4 U1.15 | length 13.9
  Top Layer w0.13: v1@762.278,218.67 762.19,218.67 762.32,218.8 762.32,219.71 762.911,220.301 762.911,223.879 762.611,224.179 CORE.63@762.611,225.38
  Bottom Layer w0.13: RN6.4@761.327,214.083 761.327,214.482 760.37,215.439 760.37,215.95 762.188,217.768 762.188,218.579 v1(762.278,218.67)
  Bottom Layer w0.2: v1(762.278,218.67) 762.325,218.716 U1.15@762.325,219.564
LCD_DATA12: CORE.61 RN5.1 U1.13 | length 13.7
  Top Layer w0.13: CORE.61@763.211,225.38 763.211,218.701 763.19,218.68 v1(763.378,218.68)
  Bottom Layer w0.13: RN5.1@762.364,214.083 762.364,214.664 762.57,214.87 763.17,214.87 764.03,215.73 764.03,217.65 763.378,218.302 v1(763.378,218.68)
  Bottom Layer w0.2: U1.13@763.325,219.564 763.325,218.733 v1(763.378,218.68)
LCD_DATA13: CORE.59 RN5.2 U1.12 | length 12.3
  Top Layer w0.13: v1@763.65,220.22 763.65,220.2 763.511,220.339 763.511,223.9 763.811,224.2 CORE.59@763.811,225.38 ; v1@763.65,220.2 v1(763.708,220.2)
  Bottom Layer w0.13: RN5.2@763.164,214.083 763.164,214.44 764.37,215.646 764.37,217.84 763.96,218.25 763.96,218.81 763.825,218.945 U1.12@763.825,219.564
  Bottom Layer w0.2: v1(763.708,220.2) 763.825,220.083 U1.12@763.825,219.564
LCD_DATA14: CORE.57 R12.2 RN5.3 U1.11 | length 36.2
  Top Layer w0.13: v1(764.25,220.506) 764.411,220.667 CORE.57@764.411,225.38
  Layer 1 w0.13: v1(764.25,220.506) 764.454,220.71 769.87,220.71 770.83,219.75 772.83,219.75 774.45,218.13 781.7,218.13 v1(784.94,214.89)
  Bottom Layer w0.13: RN5.3@763.964,214.083 763.964,214.57 764.708,215.314 764.708,217.989 764.26,218.437 764.26,219.5 U1.11@764.325,219.564 764.325,220.431 v1(764.25,220.506) ; R12.2@784.86,215.973 784.94,215.893 v1(784.94,214.89)
LCD_DATA15: CORE.55 RN5.4 U1.10 | length 12.5
  Top Layer w0.13: v1@764.758,218.74 764.711,218.787 764.711,223.96 765.011,224.26 CORE.55@765.011,225.38
  Bottom Layer w0.13: RN5.4@764.765,214.083 764.765,214.946 765.008,215.19 765.008,218.34 v1(764.728,218.62) 764.785,218.676 U1.10@764.785,219.564
LCD_DATA16: CORE.29 RN2.3 U1.61 | length 15.4
  Top Layer w0.13: v1(772.378,221.65) 772.34,221.65 772.25,221.56 772.25,223.85 772.811,224.411 CORE.29@772.811,225.38
  Bottom Layer w0.13: U1.61@769.925,221.665 769.94,221.65 v1(772.378,221.65) 773.02,221.65 773.988,220.682 773.988,219.24 774.276,218.953 RN2.3@774.276,214.083
LCD_DATA17: CORE.65 RN6.3 U1.16 | length 13.2
  Top Layer w0.13: v1(761.65,218.86) 761.755,218.965 761.755,220.269 761.59,220.434 761.59,223.864 762.011,224.285 CORE.65@762.011,225.38
  Bottom Layer w0.13: RN6.3@760.527,214.083 760.527,214.333 760.07,214.79 760.07,216.074 761.65,217.654 v1(761.65,218.86)
  Bottom Layer w0.2: v1(761.65,218.86) 761.825,219.035 U1.16@761.825,219.564
LCD_DATA18: CORE.31 RN2.2 U1.62 | length 14.4
  Top Layer w0.13: v1(772.078,221.07) 771.921,221.07 771.911,221.06 771.911,224.05 772.211,224.35 CORE.31@772.211,225.38
  Bottom Layer w0.13: U1.62@769.925,221.164 771.984,221.164 v1(772.078,221.07) 773.476,219.672 RN2.2@773.476,214.083
LCD_DATA19: CORE.49 RN4.2 U1.8 | length 12.8
  Top Layer w0.13: v1@765.81,218.73 765.81,219.11 766.811,220.111 CORE.49@766.811,225.38
  Bottom Layer w0.13: v1@765.81,218.73 765.81,219.55 U1.8@765.825,219.564 ; v1(765.85,218.63) 765.79,218.57 765.79,215.181 766.602,214.37 RN4.2@766.602,214.083
LCD_DATA20: CORE.67 RN6.2 U1.17 | length 12.7
  Top Layer w0.13: v1(761.178,219.53) 761.184,219.53 v1@761.214,219.56 ; v1@761.28,219.56 v1@761.214,219.56 ; CORE.67@761.411,225.38 761.411,224.109 761.29,223.988 761.29,219.743 761.214,219.667 v1@761.214,219.56
  Bottom Layer w0.13: RN6.2@759.727,214.083 759.77,214.126 759.77,216.199 761.178,217.607 v1(761.178,219.53)
  Bottom Layer w0.2: v1(761.178,219.53) 761.178,219.59 761.225,219.636 U1.17@761.225,220.164
LCD_DATA21: CORE.33 RN2.1 U1.63 | length 14.1
  Top Layer w0.13: CORE.33@771.611,225.38 771.611,220.649 v1(771.62,220.64)
  Bottom Layer w0.13: U1.63@769.925,220.665 769.949,220.64 v1(771.62,220.64) 771.673,220.587 772.137,220.587 773.176,219.548 773.176,215.326 772.67,214.82 772.67,214.089 RN2.1@772.676,214.083
LCD_DATA22: CORE.51 RN4.1 U1.9 | length 12.8
  Top Layer w0.13: v1(765.308,218.98) v1(765.308,218.98) v1@765.32,218.97 ; v1@765.32,218.88 v1@765.32,218.97 ; CORE.51@766.211,225.38 766.211,224.15 766.511,223.85 766.511,220.235 765.32,219.044 v1@765.32,218.97
  Bottom Layer w0.13: U1.9@765.325,219.564 765.308,219.548 v1(765.308,218.98) 765.308,215.239 765.802,214.746 RN4.1@765.802,214.083
LCD_DATA23: CORE.69 RN6.1 U1.18 | length 13.3
  Top Layer w0.13: v1(760.5,220.16) 760.99,220.65 760.99,224.061 760.811,224.24 CORE.69@760.811,225.38
  Bottom Layer w0.13: RN6.1@758.927,214.083 758.927,214.497 759.47,215.04 759.47,216.323 760.5,217.353 v1(760.5,220.16)
  Bottom Layer w0.2: v1(760.5,220.16) 760.5,220.42 760.745,220.665 U1.18@761.225,220.665
LCD_DE: CORE.70 RN7.8 U1.20 | length 14.3
  Top Layer w0.13: v1(760.32,221.61) 759.94,221.23 759.94,220.05 760.511,219.479 CORE.70@760.511,217.18
  Bottom Layer w0.13: RN7.8@757.89,214.083 757.89,214.22 759.17,215.5 759.17,216.447 760,217.277 760,221.29 v1(760.32,221.61) 760.375,221.665 U1.20@761.225,221.665
LCD_EN: CORE.72 Display.1 | length 59.5
  Top Layer w0.13: v1(759.2,217.64) 759.2,217.63 759.461,217.63 CORE.72@759.911,217.18
  Layer 1 w0.13: v1(759.2,217.64) 758.98,217.64 757.94,216.6 757.94,214.94 758.61,214.27 771.46,214.27 772.12,214.93 781.15,214.93 784.11,211.97 784.11,191.58 v1(783.84,191.31)
  Bottom Layer w0.13: Display.1@779.871,188.319 783.049,188.319 783.84,189.11 v1(783.84,191.31)
LCD_HSYNC: CORE.66 RN7.6 U1.22 | length 18.6
  Top Layer w0.13: v1(761.458,215.43) v1@761.469,215.44 ; v1@761.47,215.44 761.48,215.43 761.51,215.43 761.51,215.94 761.711,216.141 CORE.66@761.711,217.18
  Layer 1 w0.13: v1@758.718,216.27 759.888,215.1 761.129,215.1 v1(761.458,215.43) 761.458,217.842 760.688,218.612 760.688,219.7 760.691,219.7 761.14,220.149 761.14,222.6 760.97,222.77 v1(760.34,222.77)
  Bottom Layer w0.13: RN7.6@756.29,214.083 756.29,214.76 757.74,216.21 758.76,216.21 758.77,216.22 758.72,216.27 v1@758.718,216.27 ; v1(760.34,222.77) 760.445,222.665 U1.22@761.225,222.665
  other v1: 758.748,216.26
LCD_PCLK: CORE.64 RN7.5 U1.4 | length 25
  Top Layer w0.13: v1(762,215.77) 762.311,216.081 CORE.64@762.311,217.18
  Layer 1 w0.13: v1@758.928,216.94 758.73,216.94 758.2,216.41 758.2,215.05 758.72,214.53 762.3,214.53 762.72,214.95 762.72,216.49 ; v1(762,215.77) 762.72,216.49 ; v1@767.878,220.14 767.349,219.61 763.48,219.61 762.8,218.93 762.8,216.57 762.72,216.49
  Bottom Layer w0.13: RN7.5@755.49,214.083 755.49,214.7 757.73,216.94 v1@758.928,216.94 ; U1.4@767.825,219.564 767.825,220.115 767.85,220.14 v1@767.878,220.14
  other v1: 759.028,216.94 767.878,220.1
LCD_SIG_H.LCD_VSYNC: CORE.68 RN7.7 U1.21 | length 16.1
  Top Layer w0.13: v1@758.69,215.63 v1(760.83,215.63) 761.111,215.911 CORE.68@761.111,217.18
  Layer 1 w0.13: v1(759.86,222.17) 760.6,222.17 760.78,221.99 760.78,221.22 759.97,220.41 759.97,218.9 761.04,217.83 761.04,215.84 v1(760.83,215.63)
  Bottom Layer w0.13: RN7.7@757.09,214.083 757.12,214.113 757.12,214.97 757.77,215.62 v1(758.69,215.62) ; v1(759.86,222.17) 759.866,222.164 U1.21@761.225,222.164
LINE_IN_L: CORE.133
LINE_IN_R: CORE.131
LINE_OUT_L: CORE.127
LINE_OUT_R: CORE.125
McASP0_ACLKX: CORE.87 PORT.33 U1.23 | length 74.9
  Top Layer w0.13: CORE.87@753.011,225.38 753.1,225.291 v1(753.1,223.05) ; v1(758.34,184.33) 765.94,176.73 v1(766.14,176.73)
  Layer 1 w0.13: v1(753.1,223.05) 754.205,224.155 760.825,224.155 v1(762.3,222.68)
  Layer 2 w0.13: v1(751.56,215.08) 751.95,215.47 751.95,222.11 752.89,223.05 v1(753.1,223.05)
  Bottom Layer w0.13: v1(751.56,215.08) 751.56,213.292 752.63,212.222 752.63,209.831 758.64,203.821 758.64,184.84 758.34,184.54 v1(758.34,184.33) ; U1.23@761.225,223.164 761.816,223.164 v1(762.3,222.68) ; PORT.33@765.27,169.85 766.51,171.09 766.51,176.36 v1(766.14,176.73)
McASP0_AXR0: CORE.91 PORT.35 U1.25 | length 78.3
  Top Layer w0.13: CORE.91@751.811,225.38 751.8,225.369 751.8,222.908 v1(753.208,221.5) ; v1(758.64,182.27) 766.56,174.35 766.56,171.1 PORT.35@767.81,169.85
  Layer 1 w0.13: v1(752.29,214.1) 752.01,214.38 752.01,220.301 v1(753.208,221.5) v1@753.208,221.518 ; v1@753.21,221.52 v1@753.208,221.518 ; v1(762.328,223.85) 761.498,224.68 753.64,224.68 752.42,223.46 752.42,222.29 753.2,221.51 v1@753.208,221.518
  Bottom Layer w0.13: v1(752.29,214.1) 752.85,214.1 753.15,213.8 753.15,210.046 759.16,204.036 759.16,182.79 v1(758.64,182.27) ; U1.25@761.225,224.164 761.966,224.164 762.33,223.8 762.33,223.83 762.328,223.832 v1(762.328,223.85)
McASP0_AXR1: CORE.93 PORT.36 U1.26 | length 76
  Top Layer w0.13: CORE.93@751.211,225.38 751.211,222.529 752.86,220.88 v1(753.34,220.88)
  Layer 1 w0.13: v1(753.34,220.88) 753.68,221.22 753.68,222.41 753.99,222.72 v1(756.19,222.72) v1@756.09,222.62 ; v1(761.148,176.02) 765.89,176.02 767.83,174.08 767.83,172.41 PORT.36@767.81,172.39
  Bottom Layer w0.13: v1(756.19,222.72) v1@756.19,222.78 ; v1@756.25,222.72 757.23,222.72 ; v1(761.148,176.02) 761.07,176.02 761.07,204.7 754.97,210.8 754.97,215.342 757.348,217.721 757.348,222.602 757.23,222.72 ; U1.26@761.225,224.665 760.865,224.665 760.71,224.51 760.71,223.55 760.35,223.19 760.166,223.19 759.696,222.72 757.23,222.72
McASP0_FSX: CORE.89 PORT.34 U1.24 | length 79.4
  Top Layer w0.13: CORE.89@752.411,225.38 752.38,225.349 752.38,223.118 v1(753.128,222.37) ; v1(758.49,183.25) 764.84,176.9 v1(764.89,176.9)
  Layer 1 w0.13: v1(752.58,215.08) 752.58,215.87 756.39,219.68 756.39,220.63 756.89,221.13 756.89,222.86 756.32,223.43 754.19,223.43 753.59,222.83 ; 753.589,222.83 v1(753.128,222.37) 753.18,222.37 753.154,222.396 753.13,222.42 753.09,222.42 752.68,222.83 752.68,223.224 753.871,224.415 760.933,224.415 762.078,223.27 v1(762.348,223.27)
  Bottom Layer w0.13: v1(752.58,215.08) 751.82,214.32 751.82,213.4 752.89,212.33 752.89,209.938 758.9,203.928 758.9,183.71 758.49,183.3 v1(758.49,183.25) ; U1.24@761.225,223.665 761.885,223.665 762.348,223.202 v1(762.348,223.27) ; v1(764.89,176.9) 765.27,176.52 PORT.34@765.27,172.39
MDIO_CLK: CORE.97
MDIO_DATA: CORE.99
MIC: CORE.135 HeadSet.1 | length 26
  Top Layer w0.13: HeadSet.1@727.73,245.74 728.68,245.74 v4(729.85,244.57) ; v4(731.75,234.8) 738.611,227.939 CORE.135@738.611,225.38
  Layer 1 w0.13: v4(729.85,244.57) 732.47,241.95 732.47,241.65 732.47,235.52 v4(731.75,234.8)
MMC0_CLK: "SD CARD.5" CORE.111 R90.1 | length 56.3
  Top Layer w0.13: CORE.111@745.811,225.38 745.811,227.531 746.26,227.98 752.243,227.98 754.263,230 v1(755.818,230)
  Layer 2 w0.13: v1(755.818,230) 775.18,230 776.72,231.54 780.28,231.54 780.88,232.14 781.86,233.12 781.86,233.76 781.63,233.99 781.07,233.99 780.77,233.69 780.77,233.13 v1(780.88,233.02)
  Bottom Layer w0.13: R90.1@752.277,222.184 752.541,221.92 753.38,221.92 753.55,222.09 753.55,225.023 753.94,225.413 753.94,229.58 754.36,230 v1(755.818,230) ; 780.134,231.347 780.134,232.274 v1(780.88,233.02)
MMC0_CMD: "SD CARD.3" CORE.109 R89.1 | length 56.1
  Top Layer w0.13: CORE.109@746.411,225.38 746.411,227.341 746.79,227.72 752.351,227.72 754.21,229.58 v1(755.328,229.58)
  Layer 2 w0.13: v1(755.328,229.58) 755.369,229.62 755.604,229.62 755.645,229.58 755.992,229.58 756.033,229.62 775.3,229.62 776.81,231.13 781.16,231.13 783.12,233.09 v1(783.88,233.09)
  Bottom Layer w0.13: R89.1@752.277,220.716 752.553,220.44 753.502,220.44 753.81,220.748 753.81,224.915 754.2,225.305 754.2,228.68 755.1,229.58 v1(755.328,229.58) ; 782.334,231.347 782.334,232.344 783.08,233.09 v1(783.88,233.09)
MMC0_D0: "SD CARD.7" CORE.113 R91.1 | length 52.7
  Top Layer w0.13: CORE.113@745.211,225.38 745.211,227.651 745.8,228.24 752.135,228.24 754.315,230.42 v1(755.408,230.42)
  Layer 2 w0.13: v1(755.408,230.42) 772.27,230.42 773.5,231.65 773.5,233.42 773.86,233.78 774.56,233.78 774.83,233.51 774.83,231.54 775.28,231.09 775.66,231.09 775.76,231.19 776.53,231.96 777.29,231.96 777.79,232.46 v1(777.79,233.04)
  Bottom Layer w0.13: R91.1@752.277,223.652 753.022,223.652 753.29,223.92 753.29,225.131 753.58,225.421 753.58,229.64 754.36,230.42 v1(755.408,230.42) ; v1(777.79,233.04) 777.79,231.491 777.934,231.347
MMC0_D1: "SD CARD.8" CORE.115 R92.1 | length 52
  Top Layer w0.13: CORE.115@744.611,225.38 744.611,227.691 745.42,228.5 752.028,228.5 754.318,230.79 754.89,230.79 754.9,230.8 754.9,230.838 v1(754.898,230.84)
  Layer 2 w0.13: v1(754.898,230.84) 772.02,230.84 772.95,231.77 772.95,234.46 773.38,234.89 775.11,234.89 775.6,234.4 775.6,233.8 775.12,233.32 775.12,232.32 775.395,232.045 776.045,232.045 776.96,232.96 776.96,233.02 v1(776.95,233.02)
  Bottom Layer w0.13: R92.1@752.277,225.12 752.89,225.12 753.32,225.55 753.32,229.872 754.287,230.84 v1(754.898,230.84) ; 776.834,231.347 776.834,232.904 v1(776.95,233.02)
MMC0_D2: "SD CARD.1" CORE.105 R87.1 | length 54.4
  Top Layer w0.13: CORE.105@747.611,225.38 747.611,226.931 747.88,227.2 752.566,227.2 754.056,228.69 v1(755.38,228.69)
  Layer 2 w0.13: v1(755.38,228.69) 774.916,228.69 775.086,228.52 777.793,228.52 779.623,230.35 784.33,230.35 785.37,231.39 v1(785.39,231.39)
  Bottom Layer w0.13: R87.1@752.277,217.78 754.33,219.832 754.33,224.7 754.72,225.09 754.72,228.03 v1(755.38,228.69) ; 784.534,231.347 784.577,231.39 v1(785.39,231.39)
MMC0_D3: "SD CARD.2" CORE.107 R88.1 | length 55.1
  Top Layer w0.13: CORE.107@747.011,225.38 747.011,227.221 747.25,227.46 752.458,227.46 754.148,229.15 v1(755.78,229.15)
  Layer 2 w0.13: v1(755.78,229.15) 774.876,229.15 775.086,229.36 775.5,229.36 776.88,230.74 782.48,230.74 v1(784.3,232.56)
  Bottom Layer w0.13: R88.1@752.277,219.248 752.678,219.248 754.07,220.64 754.07,224.808 754.46,225.198 754.46,228.45 755.16,229.15 v1(755.78,229.15) ; 783.434,231.347 783.51,231.423 783.51,232.24 783.83,232.56 v1(784.3,232.56)
"Net4G Module_1": "4G Module.1" R47.1 | length 8.4
  Bottom Layer w0.3: R47.1@703.61,228.632 703.61,229.37 704.05,229.81 707.48,229.81 708.16,230.49 708.16,233.16
"Net4G Module_7": "4G Module.7" R50.1 R55.1 | length 3.8
  Bottom Layer w0.3: R50.1@710.077,235.58 710.57,235.58 ; 710.56,233.16 710.57,233.17 710.57,235.58 ; R55.1@711.433,235.58 710.57,235.58
"Net4G Module_8": "4G Module.8" RN8.5 | length 39.8
  Bottom Layer w0.13: 710.96,223.96 710.96,219.976 720.66,210.276 720.66,201.223 717.66,198.223 717.66,193.13 715.59,191.06 RN8.5@715.59,190.285
"Net4G Module_10": "4G Module.10" RN8.6 | length 39.3
  Bottom Layer w0.13: 711.76,223.96 711.76,219.544 720.92,210.384 720.92,201.115 717.98,198.175 717.98,192.81 716.39,191.22 RN8.6@716.39,190.285
"Net4G Module_12": "4G Module.12" RN8.7 | length 38.9
  Bottom Layer w0.13: 712.56,223.96 712.56,219.112 721.18,210.492 721.18,201.008 718.32,198.148 718.32,192.1 717.19,190.97 RN8.7@717.19,190.285
"Net4G Module_14": "4G Module.14" RN8.8 | length 38.5
  Bottom Layer w0.13: 713.36,223.96 713.36,218.679 721.44,210.599 721.44,200.9 718.62,198.08 718.62,191.75 717.99,191.12 RN8.8@717.99,190.285
"Net4G Module_20": "4G Module.20" R48.1 | length 3.9
  Bottom Layer w0.3: R48.1@717.63,220.567 718.96,221.897 718.96,223.96
"Net4G Module_22": "4G Module.22" C19.2 R49.1 | length 5.2
  Bottom Layer w0.3: 719.76,223.96 719.76,221.257 R49.1@719.1,220.597 720.632,220.597 C19.2@720.636,220.601
NetC13_2: C13.2 LAN.1 | length 10.6
  Bottom Layer w0.13: C13.2@747.012,237.55 748.62,237.55 751.64,234.53 LAN.1@751.64,229.81
NetC14_1: C14.1 Q3.3 U11.1
  other v1: 714.47,192.43 715.16,192.45 714.45,193.07 715.15,193.06
NetC33_1: C33.1 R67.1 R69.2 U2.5 | length 32.2
  Top Layer w0.3: v1(701.67,196.81) R67.1@702.665,196.81 ; v1(701.67,198.5) R69.2@702.693,198.5 ; v1(713.56,191.06) 713.52,191.06 713.52,190.678 715.373,188.825 718.855,188.825 720.282,190.252 U2.5@720.973,190.252 720.973,191.885 C33.1@720.968,191.89
  Layer 1 w0.3: v1(701.67,196.81) 701.67,197.655 ; v1(701.67,198.5) 701.67,197.655 ; v1(713.56,191.06) 713.63,191.13 713.63,194.65 709.66,198.62 703.44,198.62 702.475,197.655 701.67,197.655
NetC36_1: C36.1 U3.1 | length 4.2
  Top Layer w0.8: C36.1@715.302,226.81 716.332,227.84 719.04,227.84 719.09,227.89
NetC36_2: C36.2 D6.2 L1.1 U3.8 | length 5.2
  Top Layer w0.8: D6.2@710.06,228.78 710.515,228.325 U3.8@713.349,228.325 713.349,227.239 C36.2@713.778,226.81
NetC43_1: C43.1 C44.1 U3.6 | length 4.2
  Top Layer w0.8: C44.1@711.312,232.32 711.292,232.3 C43.1@711.292,231.04 711.467,230.865 U3.6@713.349,230.865 713.354,230.86 U3.6@714.14,230.86
NetC43_2: C43.2 R75.1 | length 1.7
  Top Layer w0.8: R75.1@708.15,230.843 709.571,230.843 C43.2@709.768,231.04
NetC45_1: C45.1 R6.1 U3.4 | length 3.7
  Top Layer w0.8: U3.4@718.531,232.135 U3.4@718.662,232.266 ; C45.1@718.662,233.77 U3.4@718.662,232.266 ; R6.1@720.663,232.33 718.726,232.33 U3.4@718.662,232.266
NetC46_1: C46.1 C47.1 L2.2 R76.2 R77.1
NetC49_1: C49.1 C50.1 L3.2 R79.2 R80.1
NetC61_1: C61.1 U7.1 | length 2.6
  Top Layer w0.3: U7.1@734.065,206.749 734.065,205.107 C61.1@734.77,204.402
NetC61_2: C61.2 U7.3 | length 4.6
  Top Layer w0.2: U7.3@735.324,206.708 U7.3@735.365,206.749
  Top Layer w0.3: C61.2@734.77,202.878 735.198,202.878 735.547,203.227 735.547,204.992 735.365,205.174 U7.3@735.365,206.749
NetC63_1: C63.1 U7.5 | length 4.8
  Top Layer w0.3: C63.1@736.51,202.878 737.078,202.878 737.29,203.09 737.29,204.33 737.287,204.333 737.287,204.913 736.665,205.535 U7.5@736.665,206.749
NetC63_2: C63.2 U7.4 | length 2.6
  Top Layer w0.3: U7.4@736.015,206.749 736.017,206.749 736.017,204.895 C63.2@736.51,204.402
NetC64_2: C64.2 U7.2 | length 4.7
  Top Layer w0.2: C64.2@731.895,208.627 732.085,208.818 734.244,208.818 734.715,208.347 U7.2@734.715,206.749
NetC65_2: C65.2 U8.16 | length 1.7
  Top Layer w0.2: C65.2@774.836,186.102 774.845,186.094 U8.16@776.487,186.094
NetC66_2: C66.2 U7.6 | length 3
  Top Layer w0.3: U7.6@737.315,206.749 737.315,205.65 738.65,204.315 C66.2@738.65,204.302
NetC69_1: C69.1 Debug.1 U8.7 U8.8 | length 24.7
  Top Layer w0.2: U8.8@779.262,188.369 779.512,188.369 U8.7@779.762,188.369 779.762,188.619 779.762,189.504 C69.1@780.551,190.293
  Top Layer w0.4: 779.512,188.369 779.762,188.619 779.789,188.646 779.789,189.34 C69.1@780.551,190.102 ; C69.1@780.551,190.293 C69.1@780.551,190.102 ; Debug.1@788.045,179.96 789.09,179.96 789.41,180.28 789.41,188.56 787.47,190.5 780.949,190.5 C69.1@780.551,190.102
NetC96_1: C96.1 R136.2 U12.14 X2.2 | length 9.8
  Top Layer w0.2: U12.14@765.802,204.115 765.802,205.313 R136.2@766.6,206.111 769.863,206.111 770.156,205.819 770.156,205.374 X2.2@769.648,204.866 ; X2.2@769.013,204.866 X2.2@769.648,204.866 ; C96.1@771.553,204.993 771.426,204.866 X2.2@769.648,204.866
NetC97_1: C97.1 R136.1 U12.15 X2.1 | length 10.9
  Top Layer w0.2: U12.15@765.302,204.115 765.302,207.125 765.863,207.686 R136.1@766.6,207.686 768.466,207.686 769.013,208.232 X2.1@769.013,209.311 769.14,209.438 C97.1@771.553,209.438
NetCp1_1: Cp1.1 F1.1 USB.D1 USB.U1 | length 11.8
  Bottom Layer w1.5: Cp1.1@763.863,241.983 F1.1@767.165,241.983 767.46,241.688 USB.D1@767.46,236.21 USB.U1@767.46,233.59
NetD7_1: D7.1 R70.1 | length 1.7
  Top Layer w0.13: R70.1@788.582,195.51 788.582,194.05 D7.1@788.773,193.859
NetL2_1: L2.1 U4.3
NetL3_1: L3.1 U5.3
NetLAN_11: LAN.11 R44.2 | length 6.5
  Bottom Layer w0.13: R44.2@746.972,240.646 750.436,240.646 LAN.11@752.554,242.764
NetLAN_13: LAN.13 R45.1 | length 5.1
  Bottom Layer w0.13: LAN.13@741.836,242.764 741.862,242.79 744.31,242.79 745.448,241.652 R45.1@745.448,240.646
NetP1_2: P1.2 U9.1 | length 23.9
  Top Layer w0.2: v1(719.54,195.28) 721.118,195.28 U9.1@721.149,195.249
  Layer 1 w0.2: P1.2@708.45,208.65 710.01,208.65 710.595,208.065 710.595,200.045 711.69,198.95 717.55,198.95 719.54,196.96 v1(719.54,195.28)
NetQ1_1: Q1.B R100.2 R102.1 | length 3.5
  Top Layer w0.2: Q1.B@728.556,198.843 728.378,199.021 R102.1@728.378,200.494 728.403,200.519 R100.2@730.131,200.519
NetQ2_3: Q2.3 R2.1 | length 2
  Top Layer w0.13: Q2.3@787.97,202.23 788.777,201.423 R2.1@788.777,200.53
NetQ3_1: Q3.1 R13.2 R14.2 | length 30.6
  Top Layer w0.2: v1(718.42,200.07) 719.44,199.05 v1(719.44,198.17)
  Bottom Layer w0.2: R13.2@709.38,197.653 709.533,197.5 Q3.1@710.87,197.5 711.91,198.54 711.91,199.91 712.76,200.76 717.73,200.76 v1(718.42,200.07) ; v1(719.44,198.17) 724.08,198.17 724.88,198.97 730.46,198.97 731.73,200.24 735.063,200.24 R14.2@735.22,200.083
NetR19_1: R19.1 R20.1 U9.4 | length 3.3
  Top Layer w0.13: U9.4@721.149,199.059 721.07,199.138 721.07,200.19 721.473,200.593 R19.1@721.473,200.91 R20.1@721.473,202.17
NetR39_1: R39.1 U1.49 | length 3.3
  Bottom Layer w0.13: U1.49@769.925,227.665 771.855,227.665 772.342,228.152 R39.1@772.973,228.152
NetR65_2: R65.2 R66.2 U2.8 | length 7.7
  Top Layer w0.3: U2.8@720.973,186.442 720.502,186.442 720.02,185.96 720.02,184.35 720.59,183.78 722.23,183.78 722.627,184.177 R65.2@722.627,184.74 R66.2@723.993,184.74
NetR71_2: R71.2 R72.1 | length 1.3
  Top Layer w0.8: R71.2@709.777,233.75 709.787,233.76 R72.1@711.123,233.76
NetR72_2: R72.2 R74.1 U3.5 | length 3.2
  Top Layer w0.8: U3.5@713.349,232.135 712.697,232.787 R72.2@712.697,233.76 R74.1@714.043,233.76
NetR73_2: R73.2 U3.3 | length 2.7
  Top Layer w0.8: U3.3@717.97,230.9 R73.2@720.683,230.9
NetR77_2: R77.2 R78.1 U4.5 | length 6.3
  Top Layer w0.5: R77.2@747.982,203.03 R78.1@747.982,204.427 747.982,207.767 748.643,208.428 749.253,208.428 U4.5@749.256,208.425
NetR80_2: R80.2 R81.1 U5.5 | length 6.1
  Top Layer w0.5: R80.2@722.605,207.153 R81.1@724.002,207.153 727.215,207.153 727.746,206.622 U5.5@727.746,205.879
NetR93_2: R93.2 U8.9 | length 2
  Top Layer w0.2: U8.9@778.762,188.369 778.762,190.129 R93.2@778.9,190.267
